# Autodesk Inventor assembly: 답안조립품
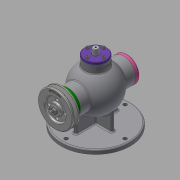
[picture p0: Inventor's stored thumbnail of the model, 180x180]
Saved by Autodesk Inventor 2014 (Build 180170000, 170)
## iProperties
Created: 2020-08
Part Number: 답안조립품
Document SubType Name: Assembly
Designer: kh
Author: kh
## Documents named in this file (18)
- C:\Users\kh\Desktop\700806V1020\답안조립품.iam
- C:\Users\kh\Desktop\700806V1020\본체.ipt
- C:\Users\kh\Desktop\700806V1020\V-벨트풀리.ipt
- C:\Users\kh\Desktop\700806V1020\너트 M8.ipt
- C:\Users\kh\Desktop\700806V1020\뒤커버.ipt
- C:\Users\kh\Desktop\700806V1020\멈춤링 15x1.ipt
- C:\Users\kh\Desktop\700806V1020\멈춤링 35x1.6.ipt
- 멈춤링 35x1.6.ipt
- C:\Users\kh\Desktop\700806V1020\베어링 6202.ipt
- 베어링 6202.ipt
- C:\Users\kh\Desktop\700806V1020\볼트 M4.ipt
- C:\Users\kh\Desktop\700806V1020\상부커버.ipt
- C:\Users\kh\Desktop\700806V1020\슬라이드.ipt
- C:\Users\kh\Desktop\700806V1020\앞커버.ipt
- C:\Users\kh\Desktop\700806V1020\오일 실 15 30 7.ipt
- C:\Users\kh\Desktop\700806V1020\칼라.ipt
- C:\Users\kh\Desktop\700806V1020\키 3x3x12.ipt
- C:\Users\kh\Desktop\700806V1020\편심축.ipt
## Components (1 placed, 1 different names)
1. V-벨트풀리:1
